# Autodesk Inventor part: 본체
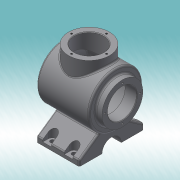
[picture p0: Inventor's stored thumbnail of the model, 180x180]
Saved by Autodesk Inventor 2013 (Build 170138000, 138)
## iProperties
Created: 2017-04
Part Number: 본체
Material: 일반
Document SubType Name: Modeling
Designer: dgall
Density: 1 g/cm^3
Author: dgall
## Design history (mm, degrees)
sketch "스케치1"
  geometry: L1 (0, 0)-(120, 0); L2 (0, 0)-(0, 27); L3 (0, 27)-(22, 27); L4 (0, 27)-(0, 38); L5 (0, 38)-(9, 38); L6 (12, 41)-(12, 47); L7 (7, 0)-(120, 0); L8 (15, 50)-(106.454, 50); L9 (25, 40)-(99.903, 40); L10 (22, 27)-(22, 37); L11 (110, 0)-(120, 0); A1 r 113 centre (7, 0) between (120, 0) and (109.166, 48.282); A2 r 103 centre (7, 0) between (110, 0) and (102.69, 38.11); A3 r 3 centre (9, 41) between (9, 38) and (12, 41); A4 r 3 centre (15, 47) between (15, 50) and (12, 47); A5 r 3 centre (106.454, 47) between (109.166, 48.282) and (106.454, 50); A6 r 3 centre (99.903, 37) between (102.69, 38.11) and (99.903, 40); A7 r 3 centre (25, 37) between (25, 40) and (22, 37); 4 further points
  constraints: 22 end point, 16 point on circle, 10 tangent, 7 centre point, 7 perpendicular, 7 point on line, 4 equal radius, 2 coincident, 1 collinear, 1 horizontal, 1 horizontal alignment, 1 parallel
  dimensions: "d0" = 120 distance of L1.start L1.end; "d1" = 27 distance of L1.start L2.end; "d2" = 22 distance of L2.end L3.end; "d3" = 11 distance of L2.end L4.end; "d4" = 12 distance of L4.end point (12, 38); "d5" = 12 distance of point (12, 38) point (12, 50); "d8" = 113 radius of A1; "d9" = 5 distance from line of L7.start L6; "d10" = 10 radial gap between concentric circles of A1 A2; "d11" = 10 distance between parallel lines of L8 L9; "d12" = 3 radius of A3
revolve "회전1" sketch "스케치1" stored, may be unused: angle "d13" = 90 deg
node "작업 평면1"
sketch "스케치2"
  geometry: L1 (-12, 47)-(-12, -47) reference; C1 r 38 at (-62, 0); C2 r 27 at (-62, 0); 1 further point
  constraints: 2 centre point, 1 coincident, 1 horizontal alignment
  dimensions: "d15" = 38 radius of C1; "d17" = 50 distance from line of C1.centre L1; "d18" = 27 radius of C2
extrude "돌출1" join sketch "스케치2" stored distance "d19" = 10; taper "d20" = 0 deg
extrude "돌출2" cut sketch "스케치2" stored distance "d21" = 10; taper "d22" = 0 deg
node "작업 평면2"
sketch "스케치3"
  geometry: L1 (-60, -82)-(60, -82); L2 (60, -82)-(60, -72); L3 (60, -72)-(21.584, -45.101); L4 (-60, -82)-(-60, -72); L5 (-60, -72)-(-21.584, -45.101); A1 r 50 centre (0, 0) between (21.584, -45.101) and (-21.584, -45.101) reference; A2 r 18 centre (0, -82) between (18, -82) and (-18, -82); 2 further points
  constraints: 10 end point, 4 point on circle, 2 point on line, 1 centre point, 1 coincident, 1 equal length, 1 horizontal, 1 midpoint, 1 parallel, 1 perpendicular, 1 vertical alignment
  dimensions: "d24" = 120 distance of L1.start L1.end; "d25" = 82 distance from line of L1 point (0, 0); "d26" = 18 radius of A2; "d27" = 10 distance of L1.end L2.end; "d28" = 10 distance of L1.start L4.end; "d29" = 55 deg angle of L2 L3
extrude "돌출3" join sketch "스케치3" stored distance "d30" = 80; taper "d31" = 0 deg
node "작업 평면3"
sketch "스케치4"
  geometry: L1 (0, -42)-(0, 0) reference; L2 (80, 0)-(0, 0) reference; L3 (0, -42)-(0, 0) reference; L4 (0, -42)-(80, -42) reference; L5 (80, 0)-(80, -42) reference; L6 (28, -32)-(28, -42); L7 (12, -32)-(12, -42); L8 (28, -42)-(16, -42); C1 r 4 at (20, -32); A1 r 8 centre (20, -32) between (28, -32) and (12, -32); 1 further point
  constraints: 6 end point, 3 point on line, 2 centre point, 2 perpendicular, 2 point on circle, 2 tangent, 1 coincident
  dimensions: "d33" = 8 radius of A1; "d34" = 20 distance from line of L1 A1.centre; "d35" = 10 distance from line of L4 A1.centre; "d36" = 4 radius of C1
  node "투영된 루프1"
extrude "돌출4" cut sketch "스케치4" stored distance "d37" = 80; taper "d38" = 0 deg
extrude "돌출5" cut sketch "스케치4" stored distance "d39" = 80; taper "d40" = 0 deg
node "작업 평면4"
sketch "스케치5" dims "d42" = 32.5
  geometry: C1 r 38 at (0, 0) reference; C2 r 27 at (0, 0) reference; 2 further points
  constraints: 2 vertical alignment, 1 coincident, 2 other
hole "구멍1" sketch "스케치5" at (0, 32.5) diameter "d44" = 3.242; stored, may be unused: countersink angle "d48" = 90 deg, drill point angle "d50" = 118 deg; dims "d45" = 8, "d46" = 4, "d47" = 2, "d49" = 10
sketch "스케치6" dims "d54" = 32.5
  geometry: C1 r 27 at (0, 0) reference; C2 r 38 at (0, 0) reference; 3 further points
  constraints: 2 vertical alignment, 1 coincident, 2 other
hole "구멍2" sketch "스케치6" at (0, 32.5) diameter "d56" = 3.459; stored, may be unused: countersink angle "d60" = 90 deg, drill point angle "d62" = 118 deg; dims "d57" = 8, "d58" = 4, "d59" = 2, "d61" = 10
fillet "모깎기1" dims "d66" = 3
fillet "모깎기2" dims "d67" = 3
fillet "모깎기3" dims "d68" = 3
node "작업 평면6"
sketch "스케치7"
  geometry: 2 further points
  constraints: 2 coincident, 1 other
feature "엠보싱1" sketch "스케치7" dims "d0" = 120, "d1" = 27, "d2" = 22, "d3" = 11, "d4" = 12, "d5" = 12, "d8" = 113, "d9" = 5, "d10" = 10, "d11" = 10, "d12" = 3, "d71" = 0.5, "d72" = 0
chamfer "모따기1" distance "d73" = 1; stored, may be unused: second distance "d74" = 2, angle "d75" = 45 deg
node "솔리드1"
mirror "대칭1"
mirror "대칭2"
pattern_circular "원형 패턴1" dims angle "d52" = 360 deg
pattern_circular "원형 패턴2" dims angle "d64" = 360 deg
other parameters: "d14" = 65, "d32" = -6, "d70" = 20.5
